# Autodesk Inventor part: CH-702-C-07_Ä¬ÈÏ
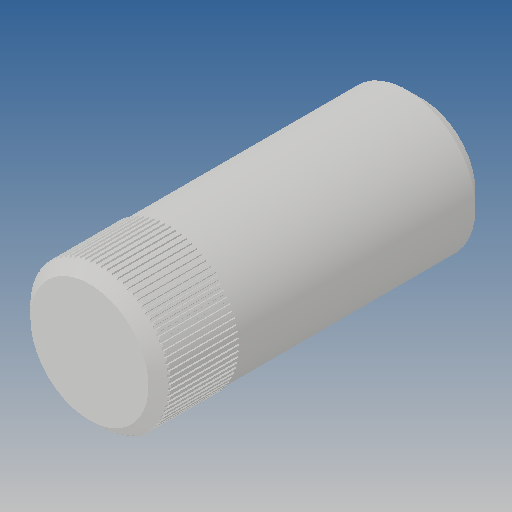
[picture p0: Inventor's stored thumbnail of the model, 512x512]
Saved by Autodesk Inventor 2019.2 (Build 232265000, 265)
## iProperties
Created: 2010-06
Part Number: CH-702-C-07_Ä¬ÈÏ
Material: Ogólny
Document SubType Name: Modeling
Designer: CADENGINEERING4
Density: 1 g/cm^3
Appearance: Domyślna
Author: CADENGINEERING4
Revision Number: ÈÎºÎ
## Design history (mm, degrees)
feature "NONE"
node "Bryła1"
